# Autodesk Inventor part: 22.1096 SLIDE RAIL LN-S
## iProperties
Created: 2007-06
Part Number: 22.1096 SLIDE RAIL LN-S
Material: UHMW, Black
Document SubType Name: Modeling
Designer: Andy Moles
Density: 0.94 g/cm^3
Mass: 27.3772 g
Surface Area: 108.664 cm^2
Volume: 29.1247 cm^3
Author: Andy Moles
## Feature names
1. Extrusion1
2. Extrusion2
3. Extrusion3
4. Mirror1
